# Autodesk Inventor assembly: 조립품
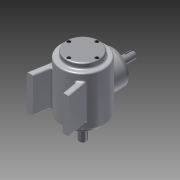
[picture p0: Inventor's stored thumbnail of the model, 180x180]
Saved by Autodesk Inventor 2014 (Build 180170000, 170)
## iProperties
Created: 2015-01
Part Number: 조립품
Document SubType Name: Assembly
Designer: Administrator
Author: Administrator
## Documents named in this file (15)
- C:\Documents and Settings\Administrator\바탕 화면\450106v1030\조립품.iam
- C:\Documents and Settings\Administrator\바탕 화면\본체.ipt
- C:\Documents and Settings\Administrator\바탕 화면\450106v1030\커버2.ipt
- C:\Documents and Settings\Administrator\바탕 화면\450106v1030\M4.ipt
- C:\Documents and Settings\Administrator\바탕 화면\450106v1030\커버.ipt
- C:\Documents and Settings\Administrator\바탕 화면\450106v1030\오일실.ipt
- C:\Documents and Settings\Administrator\바탕 화면\450106v1030\베어링 6203.ipt
- C:\Documents and Settings\Administrator\바탕 화면\450106v1030\서브 축.ipt
- 서브 축.ipt
- C:\Documents and Settings\Administrator\바탕 화면\450106v1030\키 4x4.ipt
- C:\Documents and Settings\Administrator\바탕 화면\450106v1030\서브 베벨기어.ipt
- C:\Documents and Settings\Administrator\바탕 화면\450106v1030\메인 축.ipt
- 메인 축.ipt
- C:\Documents and Settings\Administrator\바탕 화면\450106v1030\메인 베벨기어.ipt
- C:\Documents and Settings\Administrator\바탕 화면\450106v1030\키 5x5.ipt
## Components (12 placed, 1 different names)
1. M4:3
2. M4:4
3. M4:5
4. M4:6
5. M4:1
6. M4:7
7. M4:8
8. M4:9
9. M4:2
10. M4:10
11. M4:11
12. M4:12
